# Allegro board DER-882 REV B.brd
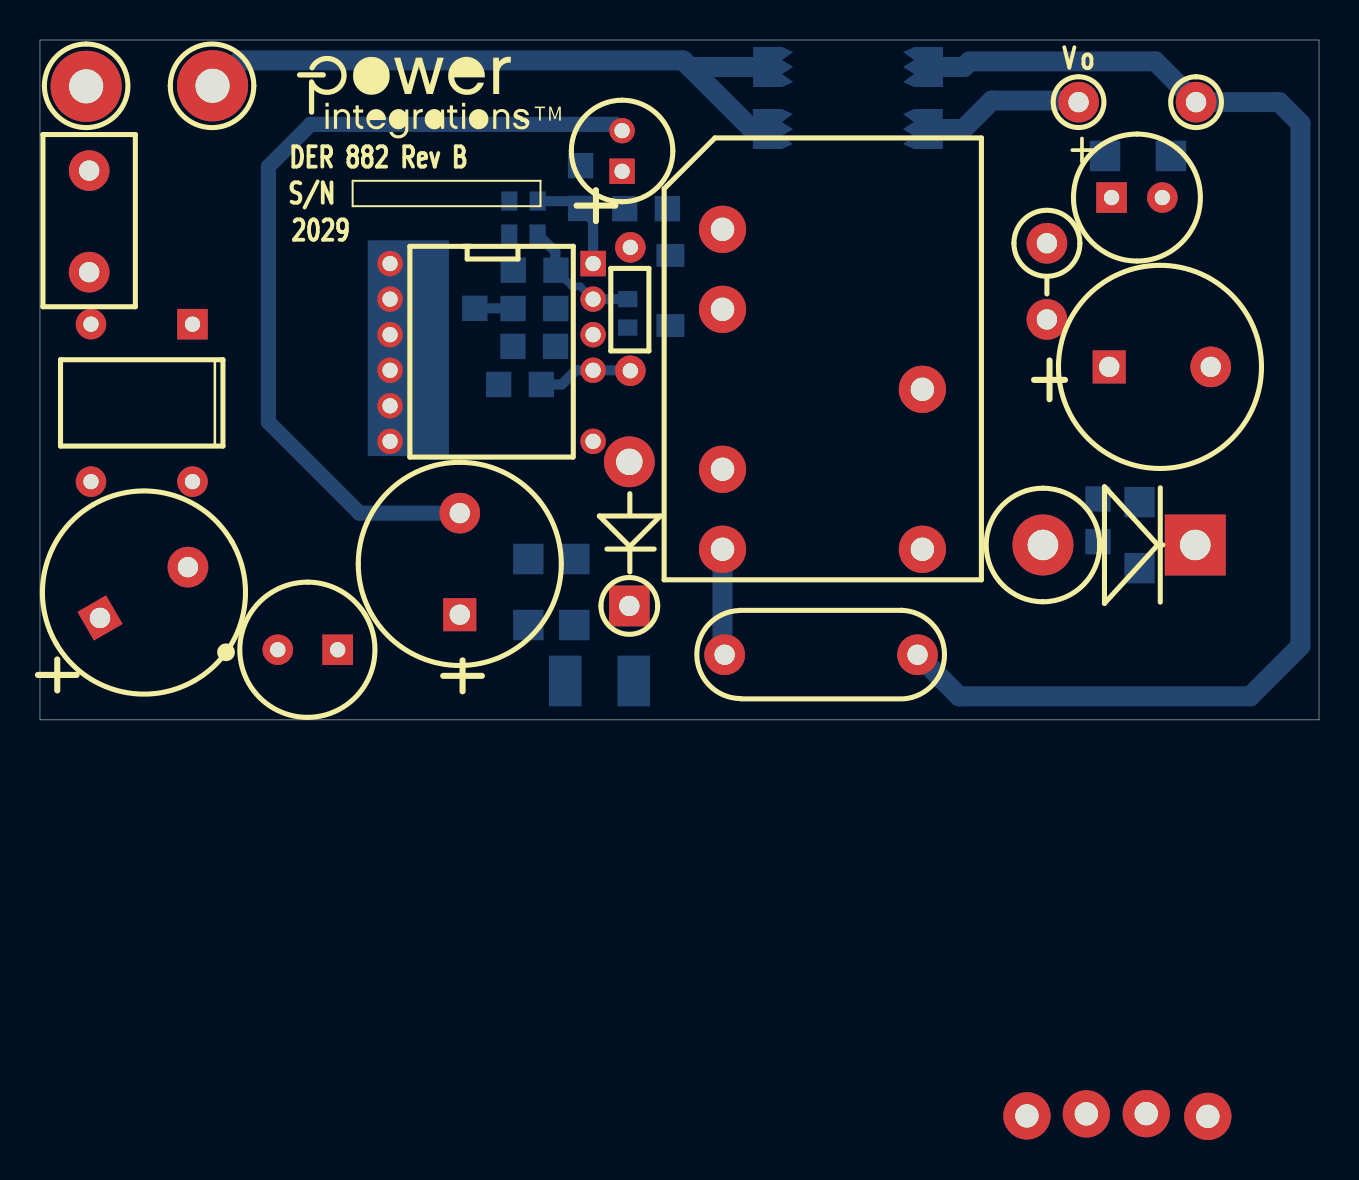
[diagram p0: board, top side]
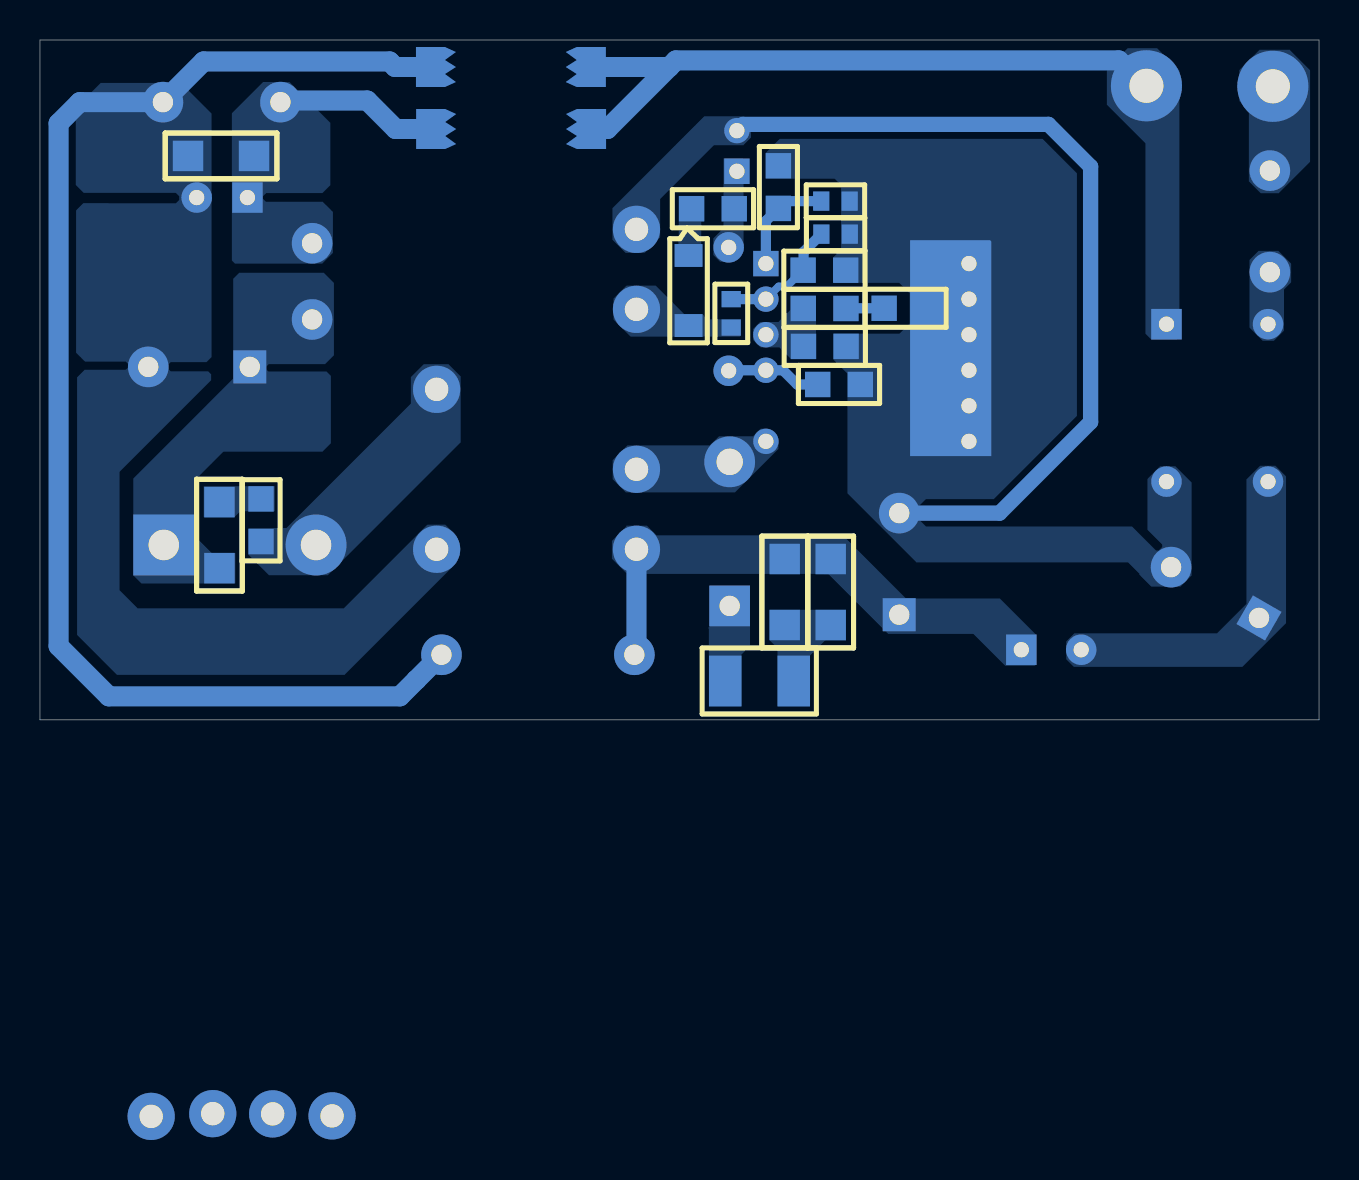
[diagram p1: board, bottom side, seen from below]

Outline 64 x 34 mm; copper layers: TOP, BOTTOM. Coordinates in mm from the lower left corner of the outline.
Outline path: 0,34 0,0 64,0 64,34 0,34

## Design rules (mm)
constraint set DEFAULT: min track width 0.508

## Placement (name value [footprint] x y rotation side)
C1  15 uF  [PIPOLCAPCYLD400LS200040]  3 5.1 30 top
C2  15 uF  [PIPOLCAPCYLD400LS200040]  21.01 5.26 90 top
C3  470 pF  [PISMC1206]  26.74 8.05 270 bottom
C4  100 uF  [PIPOLCAPCYLD250LS100030]  53.62 26.12 0 top
C5  4.7 uF  [PISMC0805]  25.09 16.77 180 bottom
C6  22 uF  [PIPOLCAPCLYD200LS80030]  29.13 27.43 90 top
C7  100 nF  [PISMC0805]  21.76 20.58 180 bottom
C8  100 pF  [PISMC0805]  25.8 18.68 180 bottom
C12  680 uF  [PIPOLCAPCYLD400LS200040]  53.5 17.65 0 top
C13  470 pF  [PISMC0805]  52.94 8.92 90 bottom
C18  220 pF  [PINPYCAPRAD500X220LS400040]  34.26 3.26 15 top
C20  33 nF  [PISMC0805]  27.05 25.58 90 bottom
C23  10 pF  [PISMC0805]  25.82 22.49 180 bottom
D1  1N4005GP-E3/54  [PIDV200X110X040DO41]  29.49 5.7 90 top
D2  SM4003PL-TP  [PI_SM_SOD-123_12]  31.55 23.22 270 bottom
D3  DF06M  [PIDAXBRIDGEDFM]  7.61 19.81 0 top
D8  STPS3150  [PIDV300X200X060DO15D0201AD]  57.81 8.75 180 top
F1  1 A  [PI_RST_MICROFUSE]  2.46 27.47 270 top
GND  BLK  [PITPKEYSTONE100X100]  57.85 30.89 0 top
L  BLK  [PITPKEYSTONE125X125]  2.31 31.68 180 top
L1  330 uH  [PI_CHOKE_RL5480-2_D2]  14.9 3.51 180 top
L2  Ferrite Bead (3.5 x 7.6 mm)  [PI12WRESD180LS675D040]  50.38 20.02 90 top
N  WHT  [PITPKEYSTONE125X125]  8.64 31.71 270 top
NOREF  -  []  -228.6 -143.78 0 top
NOREF#2  -  []  -150.78 55.23 0 top
NOREF#3  -  []  12.88 33.64 0 top
NOREF#4  -  []  0 34 0 top
NOREF#5  -  []  64 0 90 top
R2  100  [PISMR1210]  26.28 1.95 0 bottom
R3  390 k  [PISMR1206]  24.43 8.05 270 bottom
R7  100 k  [PISMR0805]  23.67 20.57 0 bottom
R8  52.3 k  [PISMR0603]  24.91 25.94 180 bottom
R9  4.3 k  [PI18WVRESD80LS100D030]  29.54 23.63 270 top
R13  20  [PISMR1206]  55.02 10.89 270 bottom
R19  53.6 k  [PISMR0603]  29.41 19.62 90 bottom
R20  11.3 k  [PISMR0603]  24.9 24.29 180 bottom
R28  27 k  [PISMR1206]  53.29 28.2 0 bottom
R29  3.9  [PISMR0805]  31.39 25.56 180 bottom
SG1  5.5mm gap  [PI_SPARK_GAP_5P5MM]  40.44 32.65 0 bottom
SG2  5.5mm gap  [PI_SPARK_GAP_5P5MM]  40.42 29.55 0 bottom
T1  EE19  [PI_BOBBIN_EE19_TF-1932_10P]  34.15 24.53 0 top
U3  LNK6774V  [PI_IC_EDIP_11-12P]  27.68 22.82 270 top
VO  RED  [PITPKEYSTONE100X100]  51.97 30.89 0 top

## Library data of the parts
C1 C2 = CAP POL: alternate symbols: (pipolcapcyld400ls200040800h)
C3 = CAP NP: alternate symbols: (pismc1206_1)
C4 = CAP POL: alternate symbols: (pipolcapcyld250ls100030h)
C5 C7 C8 C13 C18 C20 C23 = CAP NP
C6 = CAP POL: alternate symbols: (pipolcapclyd200ls80030h)
C12 = CAP POL: alternate symbols: (pipolcapclyd395x630ls200030h)
D1 = DIODE: alternate symbols: (pidv200x110x040do41A,pidax475x125040do41,pidv200x110x040do41wbead,pidax390x125040do41)
D2 = DIODE
D3 = DIODE BRIDGE_+-~~
D8 = DIODE SCHOTTKY: alternate symbols: (pidax800x225060do15do201ad,pidv300x200x060do14wbead)
F1 = FUSE: alternate symbols: (pirstmicrofusehoz)
GND L N VO = TESTPOINT
L1 = INDUCTOR_DOT2: alternate symbols: (pi_choke_RL5480-2H_d2)
L2 = INDUCTOR: alternate symbols: (pi12wvresd180ls150d040,pi12wvresd180ls200d040,pi12wvresd180ls250d040)
R2 R3 R7 R8 R13 R19 R20 R28 R29 = R
R9 = R: alternate symbols: (pi18wresd080ls300d030)
SG1 SG2 = SPARK_GAP
T1 = BEE19_10P/GENERIC
U3 = LNKHP_eDIP_eSOP

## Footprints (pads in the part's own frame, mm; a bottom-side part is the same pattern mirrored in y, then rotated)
PI12WRESD180LS675D040
  round 2.032 hole 1.016: 1(0,0) 2(3.81,0)
PI18WVRESD80LS100D030
  round 1.524 hole 0.762: 1(0,0) 2(6.172,0)
PI_BOBBIN_EE19_TF-1932_10P
  round 2.362 hole 1.168: 1(0,0) 2(0,-4) 3(24.283,-44.359) 4(0,-11.999) 5(0,-15.999) 6(10,-15.999) 7(15.232,-44.333) 8(10,-8.001) 9(18.204,-44.234) 10(21.201,-44.221)
PI_CHOKE_RL5480-2_D2
  rect 1.524x1.524 hole 0.762: 1(0,0)
  round 1.524 hole 0.762: 2(2.997,0)
PI_IC_EDIP_11-12P
  rect 1.27x1.27 hole 0.762: 1(0,0)
  round 1.27 hole 0.762: 2(1.778,0) 3(3.556,0) 4(5.334,0) 6(8.89,0) 7(8.89,-10.16) 8(7.112,-10.16) 9(5.334,-10.16) 10(3.556,-10.16) 11(1.778,-10.16) 12(0,-10.16)
PI_RST_MICROFUSE
  round 2.032 hole 1.016: 1(0,0) 2(5.08,0)
PI_SM_SOD-123_12
  rect 1.143x1.397 smd: 1(0,0) 2(3.505,0)
PI_SPARK_GAP_5P5MM
  custom 0.5x0.5 smd: 1(-3.75,0) 2(3.75,0)
PIDAXBRIDGEDFM
  rect 1.524x1.524 hole 0.762: 1(0.025,-0.025)
  round 1.524 hole 0.762: 2(-5.055,-0.025) 3(0.025,-7.899) 4(-5.055,-7.899)
PIDV200X110X040DO41
  rect 2.032x2.032 hole 1.016: 1(0,0)
  round 2.54 hole 1.321: 2(7.206,0)
PIDV300X200X060DO15D0201AD
  rect 3.048x3.048 hole 1.524: 1(0,0)
  round 3.048 hole 1.524: 2(7.62,0)
PINPYCAPRAD500X220LS400040
  round 2.032 hole 1.016: 1(0,0) 2(9.323,-2.498)
PIPOLCAPCLYD200LS80030
  rect 1.27x1.27 hole 0.762: 1(0,0)
  round 1.27 hole 0.762: 2(2.032,0)
PIPOLCAPCYLD250LS100030
  rect 1.524x1.524 hole 0.762: 1(0,0)
  round 1.524 hole 0.762: 2(2.54,0)
PIPOLCAPCYLD400LS200040
  rect 1.651x1.651 hole 1.016: 1(0,0)
  round 2.032 hole 1.016: 2(5.08,0)
PISMC0805
  rect 1.27x1.27 smd: 1(0,0) 2(2.134,0)
PISMC1206
  rect 1.524x1.524 smd: 1(0,0) 2(3.302,0)
PISMR0603
  rect 0.813x0.965 smd: 1(0,0) 2(1.422,0)
PISMR0805
  rect 1.27x1.27 smd: 1(0,0) 2(2.134,0)
PISMR1206
  rect 1.524x1.524 smd: 1(0,0) 2(3.302,0)
PISMR1210
  rect 1.626x2.54 smd: 1(0,0) 2(3.429,0)
PITPKEYSTONE100X100
  round 2.032 hole 1.016: 1(0,0)
PITPKEYSTONE125X125
  round 3.556 hole 1.702: 1(0,0)

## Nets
SOURCE: U3.8 U3.9 U3.10 U3.11 U3.12
N00259: D3.1 N.1 SG1.1 SG2.1
N00630: C1.1 D3.4 L1.2
N00726: C2.1 C3.1 C18.1 L1.1 R3.1 T1.5
N00888: C1.2 C2.2 C5.2 C6.2 C7.2 C8.2 C20.2 C23.2 D3.3 R8.2 R20.2 T1.1 U3.7(S7)
N01419: C3.2 R2.1 R3.2
N01721: D1.1 R2.2
N01734: D1.2 T1.4 U3.6
N02114: C20.1 R8.1 U3.1
N02454: C8.1 R7.2 U3.3
N02521: C7.1 R7.1
N02815: C23.1 R19.2 R20.1 U3.2
N03133: D2.2 R19.1 T1.2
N03607: C6.1 R9.1 R29.2
N03667: C5.1 R9.2 U3.4
N04837: C12.1 D8.1 L2.1 R13.2
N04849: C13.1 D8.2 T1.8
N05156: C4.1 L2.2 R28.1 SG2.2 VO.1
N05219: C4.2 C12.2 C18.2 GND.1 R28.2 SG1.2 T1.6
N08385: D3.2 F1.2
N14611: C13.2 R13.1
N4395058: D2.1 R29.1
N4400229: F1.1 L.1

Pads without a net: T1 3 7 9 10

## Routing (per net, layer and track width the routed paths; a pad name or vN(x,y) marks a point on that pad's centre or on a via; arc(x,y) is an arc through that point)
N00259: length 34
  BOTTOM w1: SG2.1 35.61,29.55 32.51,32.65 ; SG1.1 32.51,32.65 ; 32.51,32.65 32.18,32.98 10.02,32.98 8.76,31.72
N00726: length 5.3
  BOTTOM w1: C18.1 34.15,3.36 T1.5
N00888: length 42.9
  BOTTOM w0.762: C6.2 28.82,29.78 13.54,29.78 11.43,27.67 11.43,14.89 15.98,10.34 C2.2
N02114: length 5.3
  BOTTOM w0.508: R8.1 26.69,25.94 C20.1 27.68,24.95 U3.1
N02521: length 1.9
  BOTTOM w0.508: R7.1 23.66,20.58 C7.1
N02815: length 6.5
  BOTTOM w0.381: U3.2 27.04,21.68 26.63,21.68 C23.1
  BOTTOM w0.508: R19.2 U3.2 27.56,21.04 ; R20.1 25.79,23.4 25.79,22.51 C23.1
N03667: length 4.8
  BOTTOM w0.508: C5.1 26.11,16.77 26.82,17.48 U3.4 29.51,17.48 R9.2
N05156: length 7.8
  BOTTOM w1: SG2.2 46.2,29.55 47.62,30.97 51.29,30.97 51.37,30.89
N05219: length 67.5
  BOTTOM w1: C18.2 45.16,2.01 45.99,1.18 60.55,1.18 63.07,3.69 63.07,29.83 62.01,30.89 GND.1 55.81,32.93 46.51,32.93 46.23,32.65 SG1.2

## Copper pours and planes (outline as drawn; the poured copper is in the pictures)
N00259 on BOTTOM: 6.99,32.47 8.1,33.59 9.58,33.59 10.62,32.55 10.62,30.77 8.69,28.84 8.69,19.31 8.38,19.01 7.14,19.01 6.99,19.16
N00630 on BOTTOM: 2.18,12.71 2.95,12.71 3.63,12.02 3.63,5.8 5.11,4.33 12.24,4.33 12.65,3.92 12.65,3.03 12.27,2.65 3.84,2.65 1.65,4.84 1.65,12.18
N00726 on BOTTOM: 33.15,9.23 33.63,9.71 34.66,9.71 34.66,9.67 35.38,8.95 35.38,8.06 34.62,7.3 24.77,7.3 24.76,7.29 24.55,7.29 21.56,4.3 17.29,4.3 15.7,2.7 14.22,2.7 14.15,2.78 14.15,4.25 15.97,6.07 20.66,6.07 23.83,9.23
N00888 on BOTTOM (solid shape): 20.46,23.97 20.46,13.19 16.4,13.19 16.4,23.93 16.46,23.99 20.45,23.99
N00888 on BOTTOM: 13.83,29.05 26.99,29.05 27.69,28.36 27.69,27.06 24.23,27.06 23.91,26.74 23.91,23.52 24.31,23.12 24.31,21.85 21.01,21.85 20.49,21.33 20.49,19.82 20.99,19.31 24.31,19.31 24.3,19.31 24.3,18.2 24.3,18.2 24.3,18.02 23.61,17.33 23.6,17.33 23.6,11.33 20.14,7.87 9.55,7.87 8.99,7.31 8.99,7.27 8.39,6.66 6.93,6.66 6.38,7.22 6.38,11.87 7.19,12.68 7.95,12.68 8.59,12.05 8.59,9.51 7.85,8.77 7.85,8.65 8.03,8.47 8.15,8.47 9.36,9.67 19.67,9.67 20.04,10.05 20.04,10.67 19.67,11.04 16.27,11.04 12.12,15.2 12.12,27.34
N00888 on BOTTOM: 33.75,23.35 34.7,23.35 35.36,24.01 35.36,25.59 30.76,30.18 28.88,30.18 28.42,29.73 28.42,29.12 28.8,28.74 30.28,28.74 32.97,26.04 32.97,24.13
N01419 on BOTTOM: 27.48,5.5 27.48,3.97 27.09,3.58 27.09,0.68 27.09,0.67 25.47,0.67 25.47,0.68 25.47,3.22 24.71,3.98 23.67,3.98 23.67,5.51 23.84,5.51 27.47,5.51
N01721 on BOTTOM: 28.47,6.71 28.47,3.69 28.91,3.26 28.91,0.67 30.53,0.67 30.53,4.56 30.57,4.59 30.51,4.66 30.51,6.71
N01734 on BOTTOM: 34.68,11.38 29.22,11.38 27.05,13.55 27.05,14.03 27.58,14.56 27.94,14.56 28.32,14.18 30.02,14.18 30.48,13.73 34.61,13.73 35.34,12.99 35.34,12.04
N02454 on BOTTOM: 25.17,18.04 26.42,18.04 27,18.63 27.94,18.63 28.32,19.01 28.32,19.54 27.97,19.9 27.05,19.9 26.44,20.51 26.44,21.22 25.17,21.22
N03133 on BOTTOM: 35.3,21.06 35.3,20.02 34.45,19.17 28.98,19.17 28.93,19.21 28.93,20.03 28.93,20.03 30.59,20.03 30.84,20.28 31.75,20.28 33.19,21.72 34.65,21.72
N03607 on BOTTOM: 30.31,24.08 29.8,24.59 29.8,28.08 28.8,28.08 28.8,23.46 29.34,22.91 29.97,22.91 30.31,23.25
N04837 on BOTTOM: 54.92,16.48 54.33,17.07 54.33,22.06 54.03,22.36 49.8,22.36 49.29,21.85 49.29,18.23 49.73,17.79 52.55,17.79 52.67,17.67 52.67,17.52 52.57,17.42 49.66,17.42 49.44,17.2 49.44,13.83 49.86,13.41 54.82,13.41 56.28,11.95 56.28,9.22 55.4,8.35 54.23,8.35 54.23,6.83 54.23,6.82 58.92,6.82 59.33,7.23 59.33,12.07 59.1,12.3
N04849 on BOTTOM: 44.8,17.79 45.44,17.14 45.44,15.82 51.33,9.93 51.67,9.59 53.56,9.59 53.57,9.59 53.57,8.26 52.54,7.23 49.6,7.23 49.35,7.48 42.95,13.88 42.95,17.18 43.56,17.79
N05156 on BOTTOM: 54.4,30.34 52.84,31.9 51.51,31.9 49.47,29.85 49.47,26.74 49.87,26.34 52.68,26.34 52.85,26.18 52.85,26.06 52.69,25.91 49.85,25.91 49.34,25.4 49.34,23.35 49.88,22.82 54.24,22.82 54.4,22.97
N05219 on BOTTOM: 60.02,12.4 55.43,16.99 55.43,17.28 55.59,17.43 57.46,17.43 57.58,17.56 57.58,17.76 57.46,17.89 55.67,17.89 55.41,18.14 55.41,30.32 56.94,31.85 60.96,31.85 62.21,30.61 62.21,26.75 61.81,26.35 57.2,26.35 57.03,26.18 57.03,26 57.2,25.84 60.56,25.84 60.56,25.84 61.83,25.84 62.19,25.48 62.19,18.36 61.75,17.92 59.71,17.92 59.6,17.81 59.6,17.61 59.6,17.61 59.71,17.51 61.76,17.51 62.14,17.13 62.14,4.25 62.11,4.22 60.15,2.25 48.76,2.25 43.16,7.85 43.16,9.21 43.72,9.76 44.61,9.76 48.8,5.58 59.11,5.58 60.02,6.48
N08385 on BOTTOM: 2.03,23.45 3.02,23.45 3.48,23 3.48,19.62 2.82,18.96 2.26,18.96 1.75,19.47 1.75,21.52 1.4,21.88 1.4,22.82
N14611 on BOTTOM: 53.97,10.43 54.27,10.13 55.8,10.13 55.81,10.15 55.81,11.69 55.76,11.69 52.25,11.69 52.25,11.69 52.25,10.43
N4395058 on BOTTOM: 30.91,26.2 32.02,26.2 32.04,26.18 32.04,24.03 32.05,24.01 32.05,22.66 30.91,22.66
N4400229 on BOTTOM: 0.45,27.91 2.02,26.34 2.91,26.34 3.51,26.93 3.51,30.47 3.99,30.95 3.99,32.5 2.97,33.51 1.47,33.51 0.45,32.49

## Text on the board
Ref Des/Silkscreen Top: S/N | DER 882 Rev B | 2029 | V | o
User.6: NOTES: PLEASE DELETE PINS | 14.  FAB HOUSE LOGO,DATE CODE TO BE IN SILK SCREEN ONLY.DO NOT USE COPPER. | 13.  MATERIAL FR4 COPPER 2oz THICKNESS 0.062"
User.8: FIGURE | FINISHED_SIZE | 30.0 | 40.0 | 46.0 | 52.0 | 60.0 | 67.0 | DRILL CHART: TOP to BOTTOM | ALL UNITS ARE IN MILS | PLATED | QTY | 23 | 2 | 13 | 10 | 1
